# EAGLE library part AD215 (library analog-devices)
120 kHz Bandwidth, Low Distortion, Isolation Amplifier Source: http://www.analog.com/static/imported-files/data_sheets/AD215.pdf
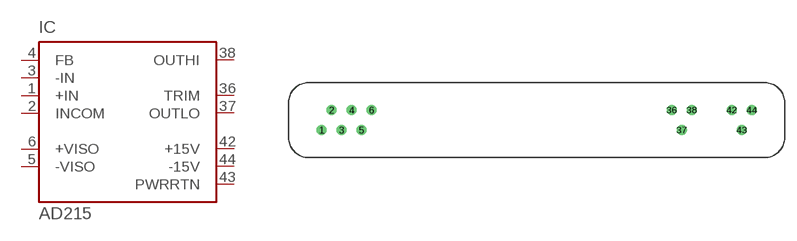
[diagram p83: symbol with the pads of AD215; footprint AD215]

Designator prefix IC

## AD215 (MF: ALTERA CORPORATION; MPN: AD215AY; OC_FARNELL: 1464281; OC_NEWARK: 09B5050)  [AD215]
1  +IN  in
2  INCOM  in
3  -IN  in
4  FB  in
5  -VISO  out
6  +VISO  out
36  TRIM  pas
37  OUTLO  out
38  OUTHI  out
42  +15V  in
43  PWRRTN  in
44  -15V  in

## Footprint AD215 (pad centres in mm)
AD215 SIP PACKAGE Source: http://www.analog.com/static/imported-files/data_sheets/AD215.pdf
drill 0.7 pad 1.27 round: 1 -27.305,-1.27; 2 -26.035,1.27; 3 -24.765,-1.27; 4 -23.495,1.27; 5 -22.225,-1.27; 6 -20.955,1.27; 36 17.145,1.27; 37 18.415,-1.27; 38 19.685,1.27; 42 24.765,1.27; 43 26.035,-1.27; 44 27.305,1.27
